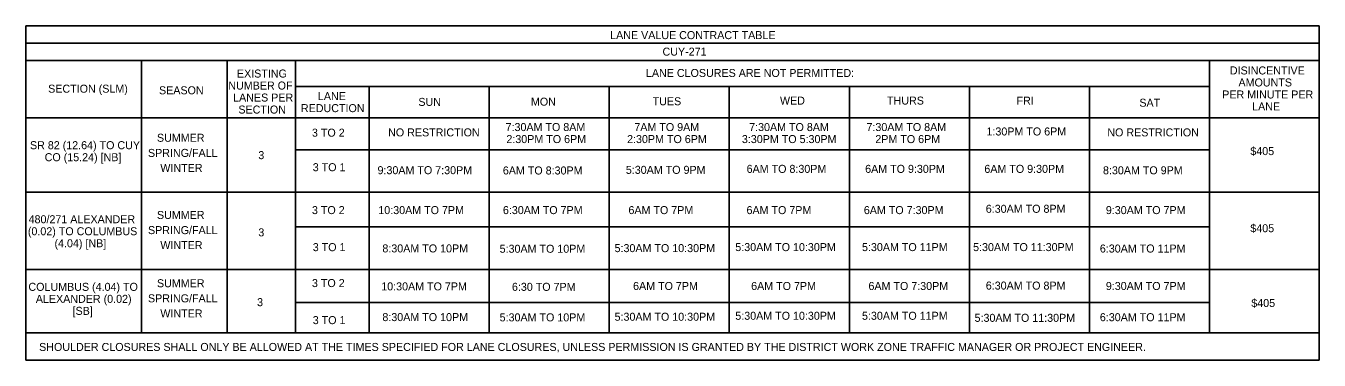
# Model space of a CAD drawing. Extents: x 0 to 49.3, y -31.9 to 22.
# Drawn here: x 26.66 to 49.28, y -9.03 to -3.18 of the extents above; entities that cross this region are included whole.
import ezdxf

# ---------------------------------------------------------------- set-up
doc = ezdxf.new("R2010")
doc.units = 0
doc.layers.add('SH_Text', color=7, linetype='Continuous')

msp = doc.modelspace()

# ---------------------------------------------------------------- linework, layer by layer
at = {"layer": 'SH_Text'}
for p, q in [((26.656, -3.182), (49.277, -3.182)), ((26.656, -3.182), (26.656, -9.028)), ((49.277, -3.182), (49.277, -9.028)), ((26.656, -3.482), (49.277, -3.482)), ((26.656, -3.789), (49.277, -3.789)), ((28.676, -3.789), (28.676, -8.548)), ((30.176, -3.789), (30.176, -8.548)), ((31.374, -3.789), (31.374, -8.548)), ((47.36, -3.789), (47.36, -8.548)), ((31.374, -4.244), (47.36, -4.244)), ((32.66, -4.252), (32.66, -8.548)), ((34.76, -4.252), (34.76, -8.548)), ((36.86, -4.252), (36.86, -8.548)), ((38.96, -4.252), (38.96, -8.548)), ((41.06, -4.252), (41.06, -8.548)), ((43.16, -4.252), (43.16, -8.548)), ((45.26, -4.252), (45.26, -8.548)), ((26.656, -4.789), (49.277, -4.789)), ((31.374, -5.35), (47.36, -5.35)), ((26.656, -6.09), (49.277, -6.09)), ((31.374, -6.699), (47.36, -6.699)), ((26.656, -7.44), (49.277, -7.44)), ((31.374, -8.019), (47.36, -8.019)), ((26.656, -8.548), (49.277, -8.548)), ((26.656, -9.028), (49.277, -9.028))]:
    msp.add_line(p, q, dxfattribs=at)

# ---------------------------------------------------------------- texts
for s, p in [('LANE VALUE CONTRACT TABLE', (36.876, -3.414)), ('CUY-271', (37.792, -3.703)), ('EXISTING ', (30.348, -4.086)), ('LANE CLOSURES ARE NOT PERMITTED: ', (37.502, -4.076)), ('DISINCENTIVE ', (47.715, -4.032)), ('SECTION (SLM)', (27.046, -4.351)), ('SEASON', (28.985, -4.379)), ('NUMBER OF', (30.197, -4.296)), ('AMOUNTS', (47.866, -4.242)), ('LANES PER ', (30.281, -4.506)), ('LANE ', (31.764, -4.481)), ('SUN', (33.521, -4.582)), ('MON', (35.49, -4.578)), ('TUES', (37.619, -4.571)), ('WED', (39.846, -4.559)), ('THURS', (41.719, -4.559)), ('FRI', (43.984, -4.56)), ('SAT', (46.132, -4.596)), ('PER MINUTE PER ', (47.582, -4.452)), ('LANE', (48.105, -4.662)), ('SECTION', (30.373, -4.716)), ('REDUCTION', (31.467, -4.691)), ('NO RESTRICTION', (32.992, -5.115)), ('7:30AM TO 8AM', (35.047, -5.022)), ('7AM TO 9AM', (37.299, -5.022)), ('7:30AM TO 8AM', (39.307, -5.022)), ('7:30AM TO 8AM', (41.359, -5.022)), ('1:30PM TO 6PM', (43.458, -5.099)), ('NO RESTRICTION', (45.572, -5.115)), ('SR 82 (12.64) TO CUY ', (26.728, -5.339)), ('SUMMER', (28.949, -5.209)), ('3 TO 2', (31.66, -5.12)), ('2:30PM TO 6PM', (35.061, -5.232)), ('2:30PM TO 6PM', (37.172, -5.232)), ('3:30PM TO 5:30PM', (39.18, -5.232)), ('2PM TO 6PM', (41.514, -5.232)), ('CO (15.24) [NB]', (26.985, -5.549)), ('SPRING/FALL', (28.792, -5.474)), ('3', (30.722, -5.513)), ('$405', (48.073, -5.442)), ('WINTER', (29.008, -5.737)), ('3 TO 1', (31.674, -5.724)), ('9:30AM TO 7:30PM', (32.807, -5.776)), ('6AM TO 8:30PM', (34.999, -5.781)), ('5:30AM TO 9PM', (37.15, -5.77)), ('6AM TO 8:30PM', (39.263, -5.753)), ('6AM TO 9:30PM', (41.336, -5.753)), ('6AM TO 9:30PM', (43.421, -5.753)), ('8:30AM TO 9PM', (45.496, -5.778)), ('3 TO 2', (31.66, -6.474)), ('10:30AM TO 7PM', (32.821, -6.474)), ('6:30AM TO 7PM', (35, -6.474)), ('6AM TO 7PM', (37.196, -6.474)), ('6AM TO 7PM', (39.261, -6.474)), ('6AM TO 7:30PM', (41.313, -6.474)), ('6:30AM TO 8PM', (43.446, -6.451)), ('9:30AM TO 7PM', (45.546, -6.474)), ('480/271 ALEXANDER ', (26.704, -6.634)), ('SUMMER', (28.949, -6.559)), ('(0.02) TO COLUMBUS ', (26.691, -6.844)), ('SPRING/FALL', (28.792, -6.824)), ('3', (30.722, -6.863)), ('$405', (48.073, -6.791)), ('(4.04) [NB]', (27.157, -7.054)), ('WINTER', (29.008, -7.087)), ('3 TO 1', (31.674, -7.122)), ('8:30AM TO 10PM', (32.892, -7.144)), ('5:30AM TO 10PM', (34.943, -7.15)), ('5:30AM TO 10:30PM', (36.953, -7.139)), ('5:30AM TO 10:30PM', (39.065, -7.121)), ('5:30AM TO 11PM', (41.281, -7.121)), ('5:30AM TO 11:30PM', (43.224, -7.121)), ('6:30AM TO 11PM', (45.441, -7.146)), ('COLUMBUS (4.04) TO ', (26.701, -7.816)), ('SUMMER', (28.949, -7.753)), ('3 TO 2', (31.66, -7.75)), ('10:30AM TO 7PM', (32.872, -7.808)), ('6:30 TO 7PM', (35.158, -7.816)), ('6AM TO 7PM', (37.277, -7.801)), ('6AM TO 7PM', (39.342, -7.801)), ('6AM TO 7:30PM', (41.394, -7.801)), ('6:30AM TO 8PM', (43.446, -7.794)), ('9:30AM TO 7PM', (45.546, -7.801)), ('ALEXANDER (0.02) ', (26.83, -8.026)), ('SPRING/FALL', (28.792, -8.017)), ('[SB]', (27.473, -8.236)), ('WINTER', (29.008, -8.281)), ('3', (30.7, -8.084)), ('$405', (48.09, -8.099)), ('3 TO 1', (31.674, -8.398)), ('8:30AM TO 10PM', (32.892, -8.345)), ('5:30AM TO 10PM', (34.943, -8.35)), ('5:30AM TO 10:30PM', (36.953, -8.339)), ('5:30AM TO 10:30PM', (39.065, -8.322)), ('5:30AM TO 11PM', (41.281, -8.322)), ('5:30AM TO 11:30PM', (43.25, -8.358)), ('6:30AM TO 11PM', (45.441, -8.347)), ('SHOULDER CLOSURES SHALL ONLY BE ALLOWED AT THE TIMES SPECIFIED FOR LANE CLOSURES, UNLESS PERMISSION IS GRANTED BY THE DISTRICT WORK ZONE TRAFFIC MANAGER OR PROJECT ENGINEER.', (26.888, -8.867))]:
    msp.add_text(s, height=0.14, dxfattribs=at).set_placement(p)

doc.saveas('drawing.dxf')
